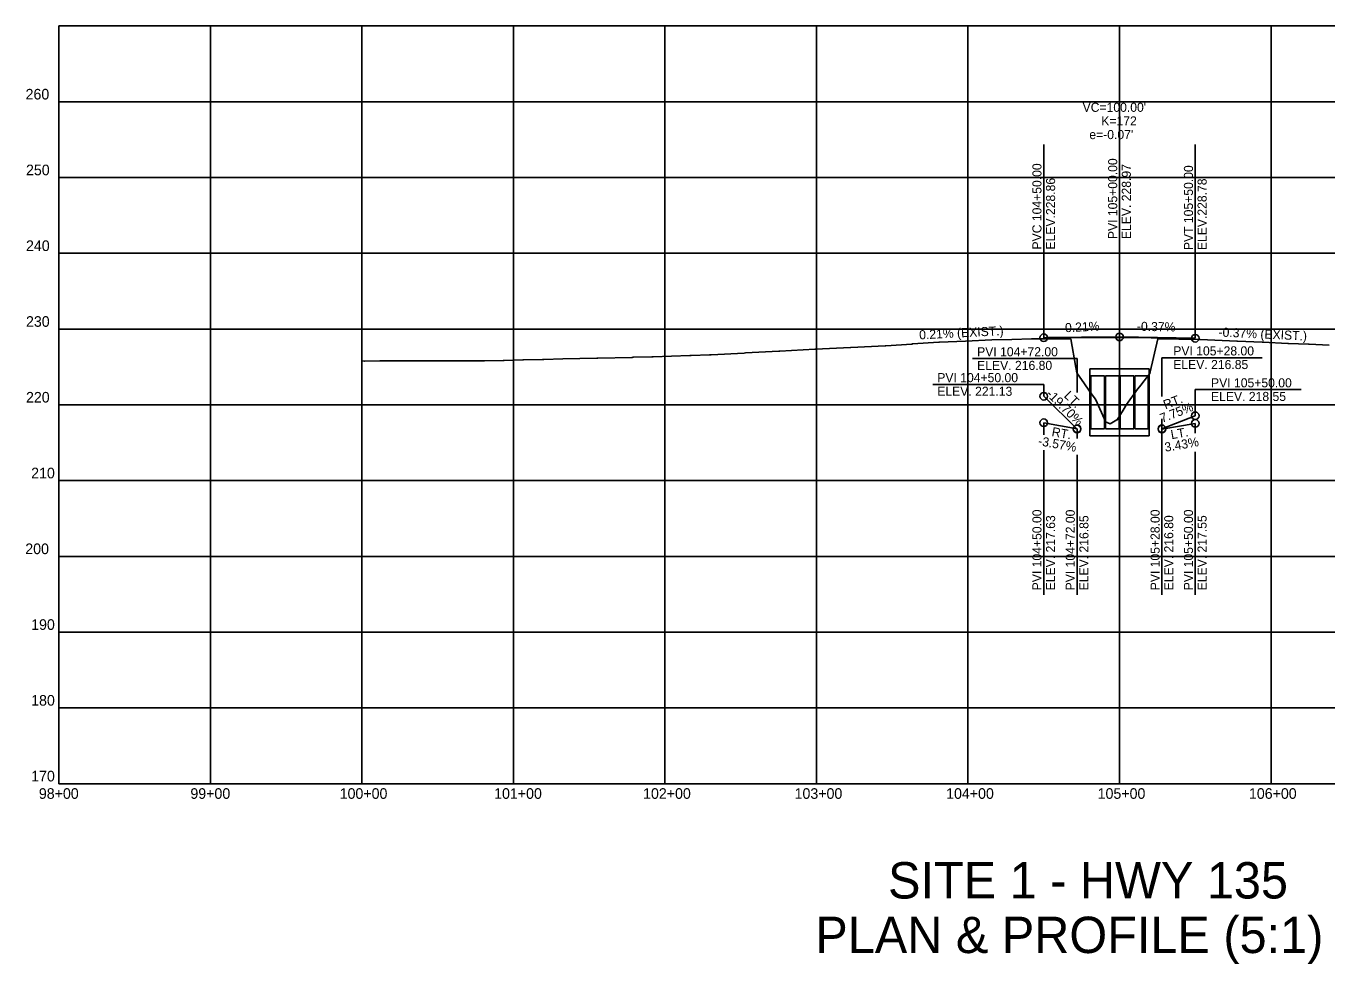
# Model space of a CAD drawing. Extents: x 1805251 to 1808760, y 516965 to 518393.
# Drawn here: x 1805251 to 1806108, y 517423 to 518042 of the extents above; entities that cross this region are included whole.
import ezdxf

# ---------------------------------------------------------------- set-up
doc = ezdxf.new("R2010")
doc.units = 0
for name, color, linetype in [('Default', 7, 'Continuous'), ('R_Axis', 7, 'Continuous'), ('R_Axis Annot', 7, 'Continuous'), ('R_Concrete', 7, 'Continuous'), ('R_Exist Surface', 7, 'Continuous'), ('R_Grid', 7, 'Continuous'), ('R_Horz Alg Annot', 7, 'Continuous'), ('R_Vert Alg', 7, 'Continuous'), ('R_Vert Alg Annot', 7, 'Continuous')]:
    doc.layers.add(name, color=color, linetype=linetype)

msp = doc.modelspace()

# ---------------------------------------------------------------- linework, layer by layer
at = {"layer": 'R_Axis'}
for q in [(1805272.2, 518042.24), (1806772.2, 517542.24)]:
    msp.add_line((1805272.2, 517542.24), q, dxfattribs=at)
at = {"layer": 'R_Concrete'}
for p, q in [((1805952.63, 517815.92), (1805952.63, 517771.75)), ((1805952.63, 517815.92), (1805991.8, 517815.92)), ((1805991.8, 517815.92), (1805991.8, 517771.75)), ((1805953.21, 517811.34), (1805962.21, 517811.34)), ((1805953.21, 517811.34), (1805953.21, 517776.34)), ((1805962.21, 517811.34), (1805962.21, 517776.34)), ((1805962.88, 517811.34), (1805962.88, 517776.34)), ((1805962.88, 517811.34), (1805971.88, 517811.34)), ((1805971.88, 517811.34), (1805971.88, 517776.34)), ((1805972.55, 517811.34), (1805972.55, 517776.34)), ((1805972.55, 517811.34), (1805981.55, 517811.34)), ((1805981.55, 517811.34), (1805981.55, 517776.34)), ((1805982.21, 517811.34), (1805982.21, 517776.34)), ((1805982.21, 517811.34), (1805991.21, 517811.34)), ((1805991.21, 517811.34), (1805991.21, 517776.34)), ((1805991.8, 517771.75), (1805952.63, 517771.75)), ((1805962.21, 517776.34), (1805953.21, 517776.34)), ((1805971.88, 517776.34), (1805962.88, 517776.34)), ((1805981.55, 517776.34), (1805972.55, 517776.34)), ((1805991.21, 517776.34), (1805982.21, 517776.34))]:
    msp.add_line(p, q, dxfattribs=at)
at = {"layer": 'R_Exist Surface'}
msp.add_lwpolyline([(1805472.2, 517821.17), (1805473.66, 517821.16), (1805473.75, 517821.16), (1805473.84, 517821.16), (1805483.93, 517821.19), (1805493.56, 517821.2), (1805493.66, 517821.2), (1805513.21, 517821.22), (1805513.49, 517821.23), (1805513.76, 517821.23), (1805533.11, 517821.26), (1805533.57, 517821.26), (1805552.54, 517821.29), (1805553.18, 517821.3), (1805565.47, 517821.59), (1805566.06, 517821.6), (1805578.4, 517821.9), (1805578.94, 517821.91), (1805591.32, 517822.21), (1805591.82, 517822.22), (1805592.32, 517822.23), (1805604.7, 517822.52), (1805627.18, 517823.04), (1805628, 517823.06), (1805650.5, 517823.57), (1805651.29, 517823.59), (1805663.45, 517823.99), (1805664.33, 517824.01), (1805676.49, 517824.41), (1805688.59, 517824.8), (1805689.59, 517824.83), (1805701.69, 517825.23), (1805702.68, 517825.27), (1805724.58, 517826.42), (1805725.32, 517826.45), (1805747.47, 517827.62), (1805747.96, 517827.65), (1805771.03, 517828.89), (1805771.46, 517828.92), (1805794.6, 517830.16), (1805794.8, 517830.17), (1805817.57, 517831.19), (1805817.91, 517831.21), (1805835.21, 517832.38), (1805835.6, 517832.4), (1805852.98, 517833.59), (1805853.3, 517833.6), (1805870.48, 517834.33), (1805870.64, 517834.34), (1805887.98, 517835.07), (1805888, 517835.07), (1805901.06, 517835.39), (1805901.08, 517835.39), (1805914.13, 517835.71), (1805914.17, 517835.71), (1805926.83, 517835.72), (1805927.09, 517835.72), (1805939.54, 517835.74), (1805940.02, 517835.75), (1805943.44, 517816.91), (1805944.09, 517813.46), (1805949.05, 517806.16), (1805951.9, 517801.89), (1805956.15, 517796.28), (1805956.64, 517795.64), (1805962.96, 517781.16), (1805962.97, 517781.12), (1805962.99, 517781.13), (1805966.1, 517779.64), (1805970.5, 517782.25), (1805970.66, 517782.27), (1805974.59, 517788.82), (1805976.76, 517792.41), (1805984.06, 517802.52), (1805984.14, 517802.62), (1805984.27, 517802.77), (1805986.23, 517805.28), (1805992.23, 517812.94), (1805992.46, 517814.06), (1805997.49, 517835.79), (1805997.91, 517835.78), (1806011.45, 517835.52), (1806011.66, 517835.52), (1806024.53, 517835.27), (1806025.42, 517835.25), (1806025.44, 517835.25), (1806049.53, 517834.31), (1806050, 517834.28), (1806066.4, 517833.52), (1806066.89, 517833.49), (1806083.26, 517832.73), (1806083.69, 517832.71), (1806096.89, 517832.19), (1806097.39, 517832.17), (1806110.51, 517831.65)], dxfattribs=at)
at = {"layer": 'R_Grid'}
for p, q in [((1805272.2, 518042.24), (1806772.2, 518042.24)), ((1805272.2, 518042.24), (1806772.2, 518042.24)), ((1805372.2, 517542.24), (1805372.2, 518042.24)), ((1805472.2, 517542.24), (1805472.2, 518042.24)), ((1805572.2, 517542.24), (1805572.2, 518042.24)), ((1805672.2, 517542.24), (1805672.2, 518042.24)), ((1805772.2, 517542.24), (1805772.2, 518042.24)), ((1805872.2, 517542.24), (1805872.2, 518042.24)), ((1805972.2, 517542.24), (1805972.2, 518042.24)), ((1806072.2, 517542.24), (1806072.2, 518042.24)), ((1805272.2, 517992.24), (1806772.2, 517992.24)), ((1805272.2, 517942.24), (1806772.2, 517942.24)), ((1805272.2, 517892.24), (1806772.2, 517892.24)), ((1805272.2, 517842.24), (1806772.2, 517842.24)), ((1805272.2, 517792.24), (1806772.2, 517792.24)), ((1805272.2, 517742.24), (1806772.2, 517742.24)), ((1805272.2, 517692.24), (1806772.2, 517692.24)), ((1805272.2, 517642.24), (1806772.2, 517642.24)), ((1805272.2, 517592.24), (1806772.2, 517592.24))]:
    msp.add_line(p, q, dxfattribs=at)
at = {"layer": 'R_Vert Alg'}
for p, q in [((1805947.2, 517836.81), (1805972.2, 517837.07)), ((1805972.2, 517837.07), (1805997.2, 517836.61)), ((1805922.2, 517780.41), (1805944.2, 517776.49)), ((1806000.2, 517776.49), (1806022.2, 517785.01))]:
    msp.add_line(p, q, dxfattribs=at)
msp.add_lwpolyline([(1805922.2, 517836.55), (1805924.28, 517836.57), (1805926.37, 517836.59), (1805928.45, 517836.61), (1805930.53, 517836.62), (1805932.62, 517836.64), (1805934.7, 517836.65), (1805936.78, 517836.67), (1805938.87, 517836.68), (1805940.95, 517836.69), (1805943.03, 517836.7), (1805945.12, 517836.71), (1805947.2, 517836.72), (1805949.28, 517836.72), (1805951.37, 517836.73), (1805953.45, 517836.73), (1805955.53, 517836.74), (1805957.62, 517836.74), (1805959.7, 517836.74), (1805961.78, 517836.73), (1805963.87, 517836.73), (1805965.95, 517836.73), (1805968.03, 517836.72), (1805970.12, 517836.72), (1805974.28, 517836.7), (1805976.37, 517836.69), (1805978.45, 517836.68), (1805980.53, 517836.67), (1805982.62, 517836.65), (1805984.7, 517836.64), (1805986.78, 517836.62), (1805988.87, 517836.6), (1805990.95, 517836.58), (1805993.03, 517836.56), (1805995.12, 517836.54), (1805997.2, 517836.52), (1805999.28, 517836.49), (1806001.37, 517836.47), (1806003.45, 517836.44), (1806005.53, 517836.41), (1806007.62, 517836.39), (1806009.7, 517836.36), (1806011.78, 517836.32), (1806013.87, 517836.29), (1806015.95, 517836.26), (1806018.03, 517836.22), (1806020.12, 517836.18), (1806022.2, 517836.15)], dxfattribs=at)
at = {"layer": 'R_Vert Alg Annot'}
for p, q in [((1805922.2, 517963.96), (1805922.2, 517836.55)), ((1805972.2, 517837.07), (1805972.2, 517963.96)), ((1806022.2, 517963.96), (1806022.2, 517836.15)), ((1805875.23, 517822.76), (1805944.2, 517822.76)), ((1805944.2, 517800.29), (1805944.2, 517822.76)), ((1806000.2, 517823.34), (1806066.24, 517823.34)), ((1806000.2, 517797.84), (1806000.2, 517823.34)), ((1805848.92, 517805.69), (1805922.2, 517805.69)), ((1805922.2, 517797.91), (1805922.2, 517805.69)), ((1805922.2, 517797.91), (1805922.2, 517805.69)), ((1805922.2, 517797.91), (1805944.2, 517776.24)), ((1806022.2, 517802.27), (1806092.03, 517802.27)), ((1806022.2, 517785.01), (1806022.2, 517802.27)), ((1805922.2, 517780.41), (1805922.2, 517772.53)), ((1806000.2, 517776.49), (1806000.2, 517782.9)), ((1806000.2, 517776.24), (1806022.2, 517780.01)), ((1806022.2, 517780.01), (1806022.2, 517773.65)), ((1805944.2, 517776.49), (1805944.2, 517770.09)), ((1806000.2, 517776.24), (1806000.2, 517666.85)), ((1805922.2, 517762.4), (1805922.2, 517666.85)), ((1806022.2, 517761.18), (1806022.2, 517666.85)), ((1805944.2, 517759.23), (1805944.2, 517666.8))]:
    msp.add_line(p, q, dxfattribs=at)
for centre in [(1805922.2, 517836.55), (1805972.2, 517837.07), (1806022.2, 517836.15), (1805922.2, 517797.91), (1805922.2, 517797.91), (1806022.2, 517785.01), (1805922.2, 517780.41), (1805944.2, 517776.49), (1805944.2, 517776.24), (1806000.2, 517776.49), (1806000.2, 517776.24), (1806022.2, 517780.01)]:
    msp.add_circle(centre, 2.5, dxfattribs=at)

# ---------------------------------------------------------------- texts
at = {"layer": 'Default'}
for s, p in [('SITE 1 - HWY 135', (1805819.44, 517466.47)), ('PLAN & PROFILE (5:1)', (1805771.44, 517430.47))]:
    msp.add_text(s, height=24, dxfattribs=at).set_placement(p)
at = {"layer": 'R_Axis Annot'}
for s, height, p in [('260', 7, (1805250.23, 517993.74)), ('250', 7, (1805250.51, 517943.74)), ('240', 7, (1805250.51, 517893.74)), ('230', 7, (1805250.51, 517843.74)), ('220', 7, (1805250.51, 517793.74)), ('210', 7, (1805253.91, 517743.74)), ('200', 7, (1805250.04, 517693.74)), ('190', 7, (1805253.91, 517643.74)), ('180', 7, (1805253.91, 517593.74)), ('170', 7, (1805253.91, 517543.74)), ('98+00', 7, (1805259, 517532.24)), ('-', 0.0001, (1805272.2, 517542.24)), ('99+00', 7, (1805359, 517532.24)), ('100+00', 7, (1805457.53, 517532.24)), ('101+00', 7, (1805559.47, 517532.24)), ('102+00', 7, (1805657.77, 517532.24)), ('103+00', 7, (1805757.77, 517532.24)), ('104+00', 7, (1805857.77, 517532.24)), ('105+00', 7, (1805957.77, 517532.24)), ('106+00', 7, (1806057.63, 517532.24))]:
    msp.add_text(s, height=height, dxfattribs=at).set_placement(p)
at = {"layer": 'R_Horz Alg Annot'}
for s, rotation, p in [('0.21% (EXIST.)', 2.93919, (1805840.15, 517835.39)), ('-0.37% (EXIST.)', 357.38472, (1806037.45, 517837.33))]:
    msp.add_text(s, height=6, rotation=rotation, dxfattribs=at).set_placement(p)
at = {"layer": 'R_Vert Alg Annot'}
for s, p in [("VC=100.00'", (1805947.84, 517985.59)), ('K=172', (1805960.17, 517976.59)), ("e=-0.07'", (1805952.28, 517967.59)), ('PVI 104+72.00', (1805878.23, 517824.26)), ('PVI 105+28.00', (1806007.66, 517824.84)), ('ELEV. 216.80', (1805878.23, 517815.26)), ('ELEV. 216.85', (1806007.66, 517815.84)), ('PVI 104+50.00', (1805851.92, 517807.19)), ('ELEV. 221.13', (1805851.92, 517798.19)), ('PVI 105+50.00', (1806032.59, 517803.77)), ('ELEV. 218.55', (1806032.59, 517794.77))]:
    msp.add_text(s, height=6, dxfattribs=at).set_placement(p)
for s, rotation, p in [('PVC 104+50.00', 90, (1805920.7, 517894.73)), ('PVI 105+00.00', 90, (1805970.7, 517901.61)), ('ELEV. 228.97', 90, (1805979.7, 517901.61)), ('PVT 105+50.00', 90, (1806020.7, 517894.33)), ('ELEV.228.86', 90, (1805929.7, 517894.73)), ('ELEV.228.78', 90, (1806029.7, 517894.33)), ('0.21%', 2.94403, (1805936.39, 517840.13)), ('-0.37%', 358.82509, (1805983.62, 517841.13)), ('-19.70%', 315.42927, (1805923.43, 517798.8)), ('LT.', 315.42927, (1805935.18, 517797.77)), ('RT.', 21.17812, (1806002.49, 517789.23)), ('7.75%', 21.17812, (1806000.3, 517780.32)), ('RT.', 349.88992, (1805927.12, 517771.71)), ('-3.57%', 349.88992, (1805918.19, 517765.67)), ('3.43%', 9.733, (1806002.48, 517761.22)), ('LT.', 9.733, (1806006.54, 517769.54)), ('PVI 104+50.00', 90, (1805920.7, 517669.85)), ('ELEV. 217.63', 90, (1805929.7, 517669.85)), ('PVI 104+72.00', 90, (1805942.7, 517669.8)), ('ELEV. 216.85', 90, (1805951.7, 517669.8)), ('PVI 105+28.00', 90, (1805998.7, 517669.85)), ('ELEV. 216.80', 90, (1806007.7, 517669.85)), ('PVI 105+50.00', 90, (1806020.7, 517669.85)), ('ELEV. 217.55', 90, (1806029.7, 517669.85))]:
    msp.add_text(s, height=6, rotation=rotation, dxfattribs=at).set_placement(p)

doc.saveas('drawing.dxf')
